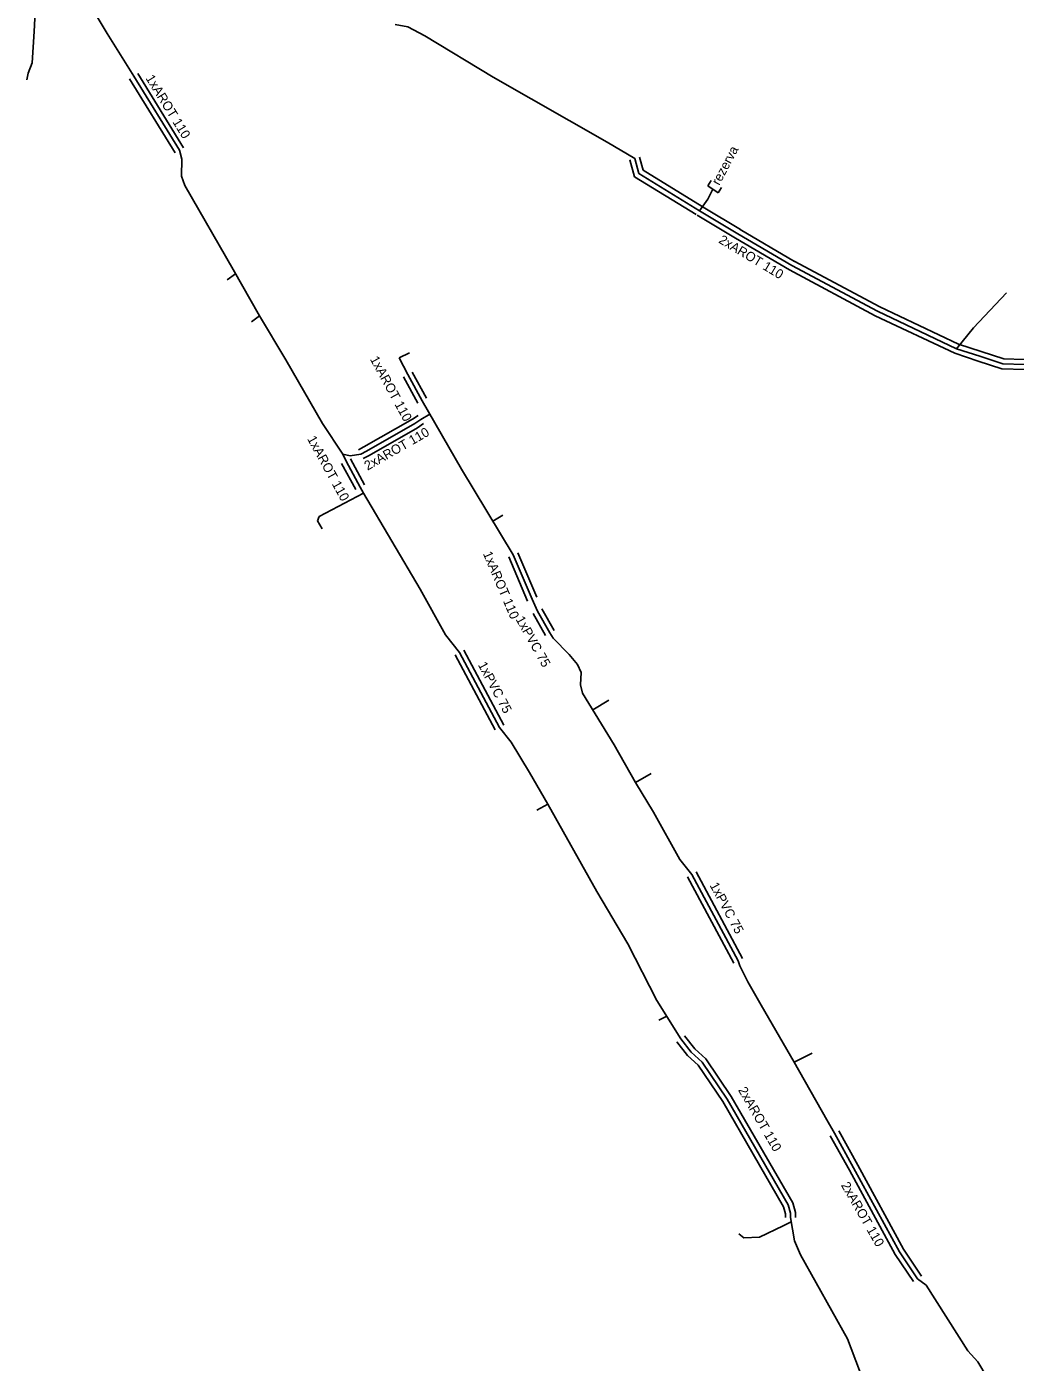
# Model space of a CAD drawing. Extents: x -651943 to -618711, y -1138561 to -1100552.
# Drawn here: x -648699.6 to -648620.2, y -1112184 to -1112076.8 of the extents above; entities that cross this region are included whole.
import ezdxf

# ---------------------------------------------------------------- set-up
doc = ezdxf.new("R2010")
doc.units = 0
doc.layers.add('KT trasa', color=7, linetype='Continuous')
doc.layers.add('KT zařízení', color=7, linetype='Continuous')

# ---------------------------------------------------------------- blocks, each defined once
blk = doc.blocks.new('TVREZ')
at = {"layer": 'KT zařízení'}
for p, q in [((-0.05, 0.05), (0, 0.05)), ((0, -0.05), (0, 0.05)), ((-0.05, -0.05), (0, -0.05))]:
    blk.add_line(p, q, dxfattribs=at)

msp = doc.modelspace()

# ---------------------------------------------------------------- linework, layer by layer
at = {"layer": 'KT trasa'}
for p, q in [((-648695.99, -1112072.53), (-648693.11, -1112077.36)), ((-648698.83, -1112074.58), (-648698.96, -1112077.21)), ((-648669.98, -1112076.63), (-648668.98, -1112076.84)), ((-648698.96, -1112077.21), (-648699.12, -1112079.72)), ((-648693.11, -1112077.36), (-648690.98, -1112080.78)), ((-648668.98, -1112076.84), (-648667.6, -1112077.55)), ((-648667.6, -1112077.55), (-648662.11, -1112080.87)), ((-648699.12, -1112079.72), (-648699.44, -1112080.55)), ((-648699.44, -1112080.55), (-648699.57, -1112081.08)), ((-648690.98, -1112080.78), (-648687.31, -1112086.74)), ((-648662.11, -1112080.87), (-648652.97, -1112086.08)), ((-648652.97, -1112086.08), (-648650.75, -1112087.39)), ((-648687.31, -1112086.74), (-648687.11, -1112087.44)), ((-648650.75, -1112087.39), (-648650.42, -1112088.6)), ((-648687.11, -1112087.44), (-648687.14, -1112088.82)), ((-648687.14, -1112088.82), (-648686.88, -1112089.56)), ((-648686.88, -1112089.56), (-648683, -1112096.3)), ((-648650.42, -1112088.6), (-648645.54, -1112091.59)), ((-648644.89, -1112090.65), (-648644.47, -1112089.86)), ((-648645.54, -1112091.59), (-648644.89, -1112090.65)), ((-648645.54, -1112091.59), (-648642.46, -1112093.44)), ((-648642.46, -1112093.44), (-648638.13, -1112095.99)), ((-648638.13, -1112095.99), (-648631.26, -1112099.66)), ((-648682.8, -1112096.66), (-648683.47, -1112097.12)), ((-648683, -1112096.3), (-648680.89, -1112100.03)), ((-648623.54, -1112100.99), (-648620.91, -1112098.17)), ((-648680.89, -1112100.03), (-648681.51, -1112100.49)), ((-648680.89, -1112100.03), (-648678.77, -1112103.55)), ((-648631.26, -1112099.66), (-648624.9, -1112102.66)), ((-648624.9, -1112102.66), (-648623.54, -1112100.99)), ((-648669.66, -1112103.39), (-648668.84, -1112102.98)), ((-648668.97, -1112104.72), (-648669.66, -1112103.39)), ((-648624.9, -1112102.66), (-648623.05, -1112103.27)), ((-648623.05, -1112103.27), (-648621.19, -1112103.87)), ((-648678.77, -1112103.55), (-648675.82, -1112108.66)), ((-648621.19, -1112103.87), (-648619.45, -1112103.92)), ((-648667.82, -1112106.83), (-648668.97, -1112104.72)), ((-648664.65, -1112112.33), (-648667.82, -1112106.83)), ((-648675.82, -1112108.66), (-648674.19, -1112111.11)), ((-648668.4, -1112108.66), (-648672.29, -1112110.88)), ((-648667.92, -1112108.34), (-648668.4, -1112108.66)), ((-648667.19, -1112107.92), (-648667.92, -1112108.34)), ((-648672.29, -1112110.88), (-648672.74, -1112111.13)), ((-648674.19, -1112111.11), (-648673.93, -1112111.69)), ((-648674.19, -1112111.11), (-648673.6, -1112111.26)), ((-648673.93, -1112111.69), (-648672.79, -1112113.77)), ((-648673.6, -1112111.26), (-648672.74, -1112111.13)), ((-648660.5, -1112119.2), (-648664.65, -1112112.33)), ((-648672.79, -1112113.77), (-648672.53, -1112114.24)), ((-648672.53, -1112114.24), (-648676.08, -1112116.13)), ((-648672.53, -1112114.24), (-648667.99, -1112121.95)), ((-648676.21, -1112116.47), (-648676.08, -1112116.13)), ((-648661.35, -1112116.03), (-648662.14, -1112116.49)), ((-648676.21, -1112116.47), (-648675.84, -1112117.11)), ((-648658.99, -1112122.76), (-648660.5, -1112119.2)), ((-648667.99, -1112121.95), (-648665.94, -1112125.61)), ((-648658.55, -1112123.72), (-648658.99, -1112122.76)), ((-648657.57, -1112125.46), (-648658.55, -1112123.72)), ((-648665.94, -1112125.61), (-648664.81, -1112127.04)), ((-648657.31, -1112125.88), (-648657.57, -1112125.46)), ((-648656.02, -1112127.19), (-648657.31, -1112125.88)), ((-648661.6, -1112133.05), (-648664.81, -1112127.04)), ((-648655.35, -1112128), (-648656.02, -1112127.19)), ((-648655.05, -1112128.64), (-648655.35, -1112128)), ((-648655.11, -1112129.63), (-648655.05, -1112128.64)), ((-648654.94, -1112130.29), (-648655.11, -1112129.63)), ((-648652.4, -1112134.44), (-648654.94, -1112130.29)), ((-648654.11, -1112131.65), (-648652.82, -1112130.85)), ((-648661.6, -1112133.05), (-648660.66, -1112134.22)), ((-648660.66, -1112134.22), (-648659.21, -1112136.67)), ((-648650.7, -1112137.46), (-648652.4, -1112134.44)), ((-648659.21, -1112136.67), (-648657.73, -1112139.21)), ((-648650.7, -1112137.46), (-648649.44, -1112136.75)), ((-648649.25, -1112139.85), (-648650.7, -1112137.46)), ((-648657.73, -1112139.21), (-648658.62, -1112139.68)), ((-648657.73, -1112139.21), (-648653.78, -1112146.22)), ((-648647.14, -1112143.65), (-648649.25, -1112139.85)), ((-648647.14, -1112143.65), (-648646.17, -1112144.84)), ((-648642.45, -1112151.77), (-648646.17, -1112144.84)), ((-648653.78, -1112146.22), (-648651.31, -1112150.42)), ((-648651.31, -1112150.42), (-648648.97, -1112154.95)), ((-648642.32, -1112152.18), (-648642.45, -1112151.77)), ((-648641.68, -1112153.46), (-648642.32, -1112152.18)), ((-648640.61, -1112155.35), (-648641.68, -1112153.46)), ((-648648.97, -1112154.95), (-648647.05, -1112158.04)), ((-648637.94, -1112159.91), (-648640.61, -1112155.35)), ((-648648.18, -1112156.22), (-648648.81, -1112156.54)), ((-648647.05, -1112158.04), (-648646.21, -1112159.1)), ((-648646.21, -1112159.1), (-648645.34, -1112159.9)), ((-648637.94, -1112159.91), (-648636.5, -1112159.19)), ((-648645.34, -1112159.9), (-648643.34, -1112162.87)), ((-648635.33, -1112164.54), (-648637.94, -1112159.91)), ((-648643.34, -1112162.87), (-648638.43, -1112171.35)), ((-648634.71, -1112165.62), (-648635.33, -1112164.54)), ((-648633.17, -1112168.38), (-648634.71, -1112165.62)), ((-648629.5, -1112175.14), (-648633.17, -1112168.38)), ((-648638.43, -1112171.35), (-648638.24, -1112172.03)), ((-648638.24, -1112172.03), (-648638.24, -1112172.37)), ((-648638.82, -1112173.05), (-648640.73, -1112173.95)), ((-648638.82, -1112173.05), (-648638.18, -1112172.73)), ((-648638.24, -1112172.37), (-648637.93, -1112174.25)), ((-648641.99, -1112174.01), (-648642.39, -1112173.69)), ((-648640.73, -1112173.95), (-648641.99, -1112174.01)), ((-648637.93, -1112174.25), (-648637.45, -1112175.36)), ((-648628.04, -1112177.3), (-648629.5, -1112175.14)), ((-648637.45, -1112175.36), (-648633.67, -1112182.11)), ((-648627.36, -1112177.82), (-648628.04, -1112177.3)), ((-648624.01, -1112183.07), (-648627.36, -1112177.82)), ((-648633.67, -1112182.11), (-648631.78, -1112187.08)), ((-648623.2, -1112183.96), (-648624.01, -1112183.07)), ((-648622.46, -1112185.22), (-648623.2, -1112183.96))]:
    msp.add_line(p, q, dxfattribs=at)
at = {"layer": 'KT zařízení'}
for p, q in [((-648690.64, -1112080.57), (-648686.97, -1112086.53)), ((-648691.32, -1112080.99), (-648687.65, -1112086.95)), ((-648650.36, -1112087.28), (-648650.08, -1112088.34)), ((-648651.14, -1112087.5), (-648650.76, -1112088.86)), ((-648650.08, -1112088.34), (-648645.33, -1112091.25)), ((-648650.76, -1112088.86), (-648645.82, -1112091.89)), ((-648645.26, -1112091.29), (-648642.25, -1112093.1)), ((-648645.74, -1112091.93), (-648642.65, -1112093.79)), ((-648642.66, -1112093.78), (-648638.32, -1112096.34)), ((-648642.27, -1112093.08), (-648637.93, -1112095.65)), ((-648637.94, -1112095.64), (-648631.07, -1112099.31)), ((-648638.32, -1112096.34), (-648631.44, -1112100.02)), ((-648631.43, -1112100.02), (-648625.05, -1112103.03)), ((-648631.08, -1112099.3), (-648624.75, -1112102.29)), ((-648624.75, -1112102.29), (-648622.93, -1112102.89)), ((-648625.05, -1112103.03), (-648623.17, -1112103.65)), ((-648622.93, -1112102.89), (-648621.12, -1112103.47)), ((-648621.12, -1112103.47), (-648619.48, -1112103.52)), ((-648667.47, -1112106.64), (-648668.62, -1112104.53)), ((-648623.17, -1112103.65), (-648621.26, -1112104.27)), ((-648621.26, -1112104.27), (-648619.42, -1112104.32)), ((-648668.17, -1112107.02), (-648669.32, -1112104.91)), ((-648668.6, -1112108.31), (-648672.5, -1112110.54)), ((-648668.14, -1112108.01), (-648668.6, -1112108.31)), ((-648667.7, -1112108.67), (-648668.2, -1112109.01)), ((-648668.2, -1112109.01), (-648672.08, -1112111.22)), ((-648672.5, -1112110.54), (-648672.93, -1112110.78)), ((-648674.28, -1112111.88), (-648673.14, -1112113.96)), ((-648673.58, -1112111.5), (-648672.44, -1112113.58)), ((-648672.08, -1112111.22), (-648672.55, -1112111.48)), ((-648659.36, -1112122.92), (-648660.87, -1112119.36)), ((-648658.62, -1112122.6), (-648660.13, -1112119.04)), ((-648657.22, -1112125.26), (-648658.2, -1112123.52)), ((-648657.92, -1112125.66), (-648658.9, -1112123.92)), ((-648661.25, -1112132.86), (-648664.46, -1112126.85)), ((-648661.95, -1112133.24), (-648665.16, -1112127.23)), ((-648642.8, -1112151.96), (-648646.52, -1112145.03)), ((-648642.1, -1112151.58), (-648645.82, -1112144.65)), ((-648646.74, -1112157.79), (-648645.92, -1112158.83)), ((-648647.36, -1112158.29), (-648646.5, -1112159.37)), ((-648645.92, -1112158.83), (-648645.03, -1112159.64)), ((-648646.5, -1112159.37), (-648645.65, -1112160.16)), ((-648645.65, -1112160.16), (-648643.68, -1112163.07)), ((-648645.03, -1112159.64), (-648643, -1112162.66)), ((-648643.68, -1112163.07), (-648638.8, -1112171.51)), ((-648643, -1112162.66), (-648638.06, -1112171.19)), ((-648632.83, -1112168.17), (-648634.36, -1112165.43)), ((-648633.51, -1112168.58), (-648635.06, -1112165.81)), ((-648629.84, -1112175.35), (-648633.51, -1112168.58)), ((-648629.16, -1112174.93), (-648632.83, -1112168.17)), ((-648638.8, -1112171.51), (-648638.64, -1112172.08)), ((-648638.64, -1112172.08), (-648638.64, -1112172.37)), ((-648638.06, -1112171.19), (-648637.84, -1112171.97)), ((-648637.84, -1112171.97), (-648637.84, -1112172.37)), ((-648627.71, -1112177.08), (-648629.16, -1112174.93)), ((-648628.37, -1112177.52), (-648629.84, -1112175.35))]:
    msp.add_line(p, q, dxfattribs=at)

# ---------------------------------------------------------------- block references
at = {"layer": 'KT zařízení', "xscale": 9.999992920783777, "yscale": 9.99999292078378, "rotation": -124.41149666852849}
msp.add_blockref('TVREZ', (-648644.47, -1112089.86), dxfattribs=at)

# ---------------------------------------------------------------- texts
at = {"layer": 'KT zařízení'}
for s, rotation, p in [('1xAROT 110', 301.6236, (-648690.05, -1112080.95)), ('rezerva', 62.1817, (-648643.96, -1112089.6)), ('2xAROT 110', 329.0091, (-648644.07, -1112094.12)), ('1xAROT 110', 298.5914, (-648672.03, -1112103.49)), ('1xAROT 110', 298.7261, (-648677.07, -1112109.89)), ('2xAROT 110', 29.7037, (-648672.2, -1112112.45)), ('1xAROT 110', 292.9846, (-648662.95, -1112119.1)), ('1xPVC 75', 299.389, (-648660.33, -1112124.37)), ('1xPVC 75', 298.1071, (-648663.36, -1112128.02)), ('1xPVC 75', 298.2267, (-648644.75, -1112145.72)), ('2xAROT 110', 300.0723, (-648642.47, -1112162.15)), ('2xAROT 110', 299.8729, (-648634.21, -1112169.78))]:
    msp.add_text(s, height=0.75, rotation=rotation, dxfattribs=at).set_placement(p)

doc.saveas('drawing.dxf')
